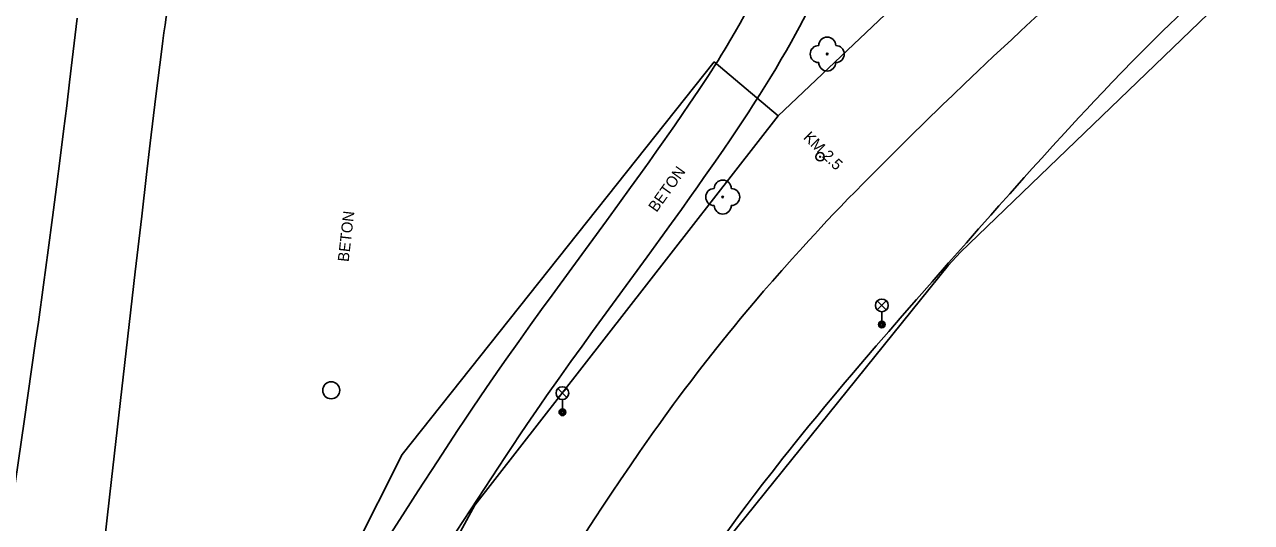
# Model space of a CAD drawing. Extents: x -540150 to -533593, y -1185082 to -1180066.
# Drawn here: x -536453.9 to -536381.8, y -1183094.3 to -1183065 of the extents above; entities that cross this region are included whole.
import ezdxf

# ---------------------------------------------------------------- set-up
doc = ezdxf.new("R2010")
doc.units = 0
for name, color, linetype in [('KN_HRAN_PARCEL', 7, 'Continuous'), ('Vrstva 10', 7, 'Continuous'), ('Vrstva 11', 7, 'Continuous'), ('Vrstva 13', 7, 'Continuous'), ('Vrstva 22', 7, 'Continuous'), ('Vrstva 25', 7, 'Continuous'), ('Vrstva 27', 7, 'Continuous'), ('Vrstva 33', 7, 'Continuous'), ('Vrstva 40', 7, 'Continuous')]:
    doc.layers.add(name, color=color, linetype=linetype)

msp = doc.modelspace()

# ---------------------------------------------------------------- linework, layer by layer
at = {"layer": 'KN_HRAN_PARCEL'}
for p, q in [((-536409.57, -1183070.345), (-536390.15, -1183051.885)), ((-536382.16, -1183062.275), (-536398.85, -1183078.365)), ((-536413.34, -1183067.155), (-536431.67, -1183090.265)), ((-536409.57, -1183070.345), (-536413.34, -1183067.155)), ((-536427.4, -1183093.245), (-536409.57, -1183070.345)), ((-536398.85, -1183078.365), (-536399.58, -1183079.145)), ((-536399.58, -1183079.145), (-536417.33, -1183101.175)), ((-536431.67, -1183090.265), (-536446.32, -1183119.215)), ((-536442.23, -1183120.325), (-536427.4, -1183093.245))]:
    msp.add_line(p, q, dxfattribs=at)
at = {"layer": 'Vrstva 10'}
for p, q in [((-536388.727, -1183067.111), (-536389.352, -1183067.751)), ((-536451.979, -1183074.516), (-536451.763, -1183072.826)), ((-536448.848, -1183092.596), (-536447.354, -1183079.508)), ((-536403.075, -1183083.016), (-536403.813, -1183083.871)), ((-536409.934, -1183091.293), (-536410.49, -1183092.012)), ((-536449.282, -1183096.334), (-536448.848, -1183092.596))]:
    msp.add_line(p, q, dxfattribs=at)
for points in [[(-536381.756, -1183060.557), (-536382.328, -1183061.051), (-536382.877, -1183061.534), (-536383.405, -1183062.004), (-536383.911, -1183062.462), (-536384.399, -1183062.908), (-536384.867, -1183063.342), (-536385.318, -1183063.765), (-536385.752, -1183064.177), (-536386.17, -1183064.577), (-536386.573, -1183064.967), (-536386.961, -1183065.346), (-536387.336, -1183065.715), (-536388.057, -1183066.433), (-536388.727, -1183067.111)], [(-536446.471, -1183071.943), (-536446.139, -1183069.184), (-536445.8, -1183066.425), (-536445.736, -1183065.931), (-536445.671, -1183065.453), (-536445.603, -1183064.991), (-536445.534, -1183064.544), (-536445.465, -1183064.111), (-536445.394, -1183063.693), (-536445.323, -1183063.288), (-536445.252, -1183062.897), (-536445.181, -1183062.518)], [(-536451.763, -1183072.826), (-536451.565, -1183071.241), (-536451.383, -1183069.755), (-536451.214, -1183068.362), (-536451.059, -1183067.055), (-536450.772, -1183064.605)], [(-536389.352, -1183067.751), (-536389.934, -1183068.355), (-536390.477, -1183068.924)], [(-536390.477, -1183068.924), (-536390.985, -1183069.46), (-536391.459, -1183069.965), (-536391.902, -1183070.441), (-536392.731, -1183071.338), (-536393.453, -1183072.129), (-536394.084, -1183072.825), (-536394.636, -1183073.437), (-536395.119, -1183073.976), (-536395.964, -1183074.923), (-536396.598, -1183075.638), (-536397.075, -1183076.177)], [(-536447.354, -1183079.508), (-536446.976, -1183076.236), (-536446.688, -1183073.783), (-536446.471, -1183071.943)], [(-536453.21, -1183083.595), (-536453.05, -1183082.469), (-536452.746, -1183080.286), (-536452.467, -1183078.238), (-536452.213, -1183076.317), (-536451.979, -1183074.516)], [(-536397.075, -1183076.177), (-536397.791, -1183076.988), (-536398.51, -1183077.805), (-536399.552, -1183078.99), (-536400.526, -1183080.097), (-536401.435, -1183081.134), (-536402.283, -1183082.105), (-536403.075, -1183083.016)], [(-536454.568, -1183093.045), (-536453.888, -1183088.32), (-536453.21, -1183083.595)], [(-536403.813, -1183083.871), (-536404.502, -1183084.673), (-536405.144, -1183085.427), (-536405.743, -1183086.136), (-536406.302, -1183086.802), (-536406.823, -1183087.428), (-536407.309, -1183088.017), (-536407.763, -1183088.571), (-536408.186, -1183089.092), (-536408.581, -1183089.582), (-536408.949, -1183090.043), (-536409.293, -1183090.477), (-536409.934, -1183091.293)], [(-536410.49, -1183092.012), (-536410.973, -1183092.645), (-536411.393, -1183093.201), (-536411.758, -1183093.691), (-536412.075, -1183094.121), (-536412.627, -1183094.878), (-536413.038, -1183095.449), (-536413.343, -1183095.88), (-536413.799, -1183096.53), (-536414.25, -1183097.185), (-536414.746, -1183097.914), (-536415.223, -1183098.621), (-536415.682, -1183099.307), (-536416.123, -1183099.973)]]:
    msp.add_lwpolyline(points, dxfattribs=at)
at = {"layer": 'Vrstva 11'}
for p, q in [((-536415.262, -1183075.853), (-536414.757, -1183075.143)), ((-536428.41, -1183088.845), (-536427.971, -1183088.18))]:
    msp.add_line(p, q, dxfattribs=at)
for points in [[(-536409.386, -1183067.016), (-536409.087, -1183066.497), (-536408.812, -1183066.008), (-536408.559, -1183065.546), (-536408.325, -1183065.112), (-536408.109, -1183064.703), (-536407.911, -1183064.318), (-536407.727, -1183063.955), (-536407.557, -1183063.613), (-536407.401, -1183063.292), (-536407.256, -1183062.989), (-536407.122, -1183062.705), (-536406.875, -1183062.168), (-536406.664, -1183061.696), (-536406.484, -1183061.28), (-536406.329, -1183060.915), (-536406.196, -1183060.594), (-536406.081, -1183060.311), (-536405.885, -1183059.815), (-536405.742, -1183059.44), (-536405.636, -1183059.158), (-536405.481, -1183058.733), (-536405.33, -1183058.305), (-536405.219, -1183057.982)], [(-536416.337, -1183071.875), (-536415.671, -1183070.921), (-536415.175, -1183070.202), (-536414.806, -1183069.66), (-536414.255, -1183068.845), (-536413.71, -1183068.025), (-536413.498, -1183067.701), (-536413.295, -1183067.385), (-536413.101, -1183067.079), (-536412.915, -1183066.78), (-536412.737, -1183066.49), (-536412.566, -1183066.208), (-536412.403, -1183065.934), (-536412.093, -1183065.4), (-536411.808, -1183064.897), (-536411.547, -1183064.421), (-536411.307, -1183063.973), (-536411.086, -1183063.551)], [(-536414.757, -1183075.143), (-536414.316, -1183074.521), (-536413.932, -1183073.975), (-536413.264, -1183073.016), (-536412.767, -1183072.294), (-536412.397, -1183071.75), (-536411.846, -1183070.93), (-536411.3, -1183070.105), (-536411.073, -1183069.757), (-536410.855, -1183069.419), (-536410.646, -1183069.091), (-536410.446, -1183068.772), (-536410.063, -1183068.152), (-536409.71, -1183067.567), (-536409.386, -1183067.016)], [(-536417.159, -1183073.037), (-536416.72, -1183072.418), (-536416.337, -1183071.875)], [(-536422.857, -1183080.883), (-536421.698, -1183079.293), (-536419.665, -1183076.511), (-536418.904, -1183075.465), (-536418.241, -1183074.548), (-536417.663, -1183073.743), (-536417.159, -1183073.037)], [(-536416.509, -1183077.582), (-536415.843, -1183076.661), (-536415.262, -1183075.853)], [(-536421.751, -1183084.792), (-536421.095, -1183083.879), (-536420.477, -1183083.025), (-536419.314, -1183081.427), (-536417.273, -1183078.632), (-536416.509, -1183077.582)], [(-536427.971, -1183088.18), (-536427.543, -1183087.539), (-536427.125, -1183086.921), (-536426.717, -1183086.323), (-536426.32, -1183085.747), (-536425.932, -1183085.19), (-536425.555, -1183084.651), (-536424.82, -1183083.612), (-536424.126, -1183082.64), (-536423.472, -1183081.732), (-536422.857, -1183080.883)], [(-536423.183, -1183086.817), (-536422.447, -1183085.77), (-536421.751, -1183084.792)], [(-536428.067, -1183094.141), (-536426.836, -1183092.258), (-536425.6, -1183090.375), (-536425.172, -1183089.728), (-536424.754, -1183089.104), (-536424.346, -1183088.502), (-536423.948, -1183087.92), (-536423.561, -1183087.359), (-536423.183, -1183086.817)], [(-536433.757, -1183097.14), (-536433.097, -1183096.098), (-536432.518, -1183095.187), (-536431.499, -1183093.597), (-536430.731, -1183092.406), (-536429.573, -1183090.624), (-536428.41, -1183088.845)], [(-536432.955, -1183101.791), (-536432.506, -1183101.071), (-536432.084, -1183100.397), (-536431.288, -1183099.137), (-536430.587, -1183098.037), (-536429.97, -1183097.076), (-536428.885, -1183095.397), (-536428.067, -1183094.141)]]:
    msp.add_lwpolyline(points, dxfattribs=at)
at = {"layer": 'Vrstva 13'}
for points in [[(-536392.666, -1183062.926), (-536393.395, -1183063.586), (-536394.076, -1183064.208), (-536394.714, -1183064.793), (-536395.31, -1183065.344)], [(-536395.31, -1183065.344), (-536395.868, -1183065.863), (-536396.911, -1183066.84), (-536397.82, -1183067.699), (-536398.613, -1183068.455), (-536399.305, -1183069.12), (-536399.91, -1183069.703), (-536400.965, -1183070.73), (-536401.754, -1183071.503), (-536402.344, -1183072.086)], [(-536402.344, -1183072.086), (-536403.228, -1183072.963), (-536404.11, -1183073.845), (-536404.582, -1183074.321), (-536405.036, -1183074.783), (-536405.472, -1183075.232), (-536405.893, -1183075.668), (-536406.298, -1183076.093), (-536406.688, -1183076.505), (-536407.063, -1183076.905), (-536407.425, -1183077.294), (-536407.773, -1183077.672), (-536408.109, -1183078.039), (-536408.755, -1183078.754)], [(-536408.755, -1183078.754), (-536409.355, -1183079.428), (-536409.912, -1183080.063)], [(-536409.912, -1183080.063), (-536410.429, -1183080.662), (-536410.911, -1183081.226), (-536411.359, -1183081.758), (-536411.776, -1183082.258), (-536412.164, -1183082.73), (-536412.526, -1183083.174), (-536412.863, -1183083.592), (-536413.178, -1183083.985), (-536413.763, -1183084.727), (-536414.27, -1183085.381), (-536414.71, -1183085.957), (-536415.093, -1183086.463), (-536415.425, -1183086.908), (-536415.715, -1183087.299)], [(-536415.715, -1183087.299), (-536416.218, -1183087.988), (-536416.592, -1183088.508)], [(-536416.592, -1183088.508), (-536416.871, -1183088.9), (-536417.287, -1183089.49), (-536417.7, -1183090.085), (-536418.277, -1183090.925), (-536418.831, -1183091.74), (-536419.364, -1183092.53), (-536419.877, -1183093.297), (-536420.37, -1183094.041), (-536420.845, -1183094.763), (-536421.302, -1183095.463), (-536421.741, -1183096.143), (-536422.165, -1183096.802)]]:
    msp.add_lwpolyline(points, dxfattribs=at)
at = {"layer": 'Vrstva 22'}
for centre in [(-536406.69, -1183066.705), (-536412.83, -1183075.115)]:
    msp.add_circle(centre, 0.05, dxfattribs=at)
for centre, start, end in [((-536406.69, -1183066.205), 359.99973, 179.99973), ((-536407.19, -1183066.705), 89.99973, 269.99973), ((-536406.19, -1183066.705), 269.99973, 89.99973), ((-536406.69, -1183067.205), 179.99973, 359.99973), ((-536412.83, -1183074.615), 360, 180), ((-536413.33, -1183075.115), 90, 270), ((-536412.33, -1183075.115), 270, 90), ((-536412.83, -1183075.615), 179.99999, 359.99999)]:
    msp.add_arc(centre, 0.5, start, end, dxfattribs=at)
at = {"layer": 'Vrstva 25'}
for radius in [0.25, 0.0303]:
    msp.add_circle((-536407.11, -1183072.745), radius, dxfattribs=at)
at = {"layer": 'Vrstva 27'}
msp.add_circle((-536435.84, -1183086.485), 0.5, dxfattribs=at)
at = {"layer": 'Vrstva 33'}
for p, q in [((-536403.745, -1183081.755), (-536403.215, -1183081.225)), ((-536403.745, -1183081.225), (-536403.215, -1183081.755)), ((-536403.48, -1183081.865), (-536403.48, -1183082.615)), ((-536422.515, -1183086.915), (-536421.985, -1183086.385)), ((-536422.515, -1183086.385), (-536421.985, -1183086.915)), ((-536422.25, -1183087.025), (-536422.25, -1183087.775))]:
    msp.add_line(p, q, dxfattribs=at)
for centre, radius in [((-536403.48, -1183081.49), 0.375), ((-536403.48, -1183082.615), 0.2), ((-536403.48, -1183082.615), 0.145), ((-536403.48, -1183082.615), 0.0876), ((-536422.25, -1183086.65), 0.375), ((-536422.25, -1183087.775), 0.2), ((-536422.25, -1183087.775), 0.145), ((-536422.25, -1183087.775), 0.0876)]:
    msp.add_circle(centre, radius, dxfattribs=at)

# ---------------------------------------------------------------- texts
at = {"layer": 'Vrstva 40'}
for s, rotation, p in [('KM 2.5', 315.55302, (-536408.131, -1183071.66)), ('BETON', 54.53062, (-536416.721, -1183076.052)), ('BETON', 83.4475, (-536434.817, -1183078.952))]:
    msp.add_text(s, height=0.65, rotation=rotation, dxfattribs=at).set_placement(p)

doc.saveas('drawing.dxf')
